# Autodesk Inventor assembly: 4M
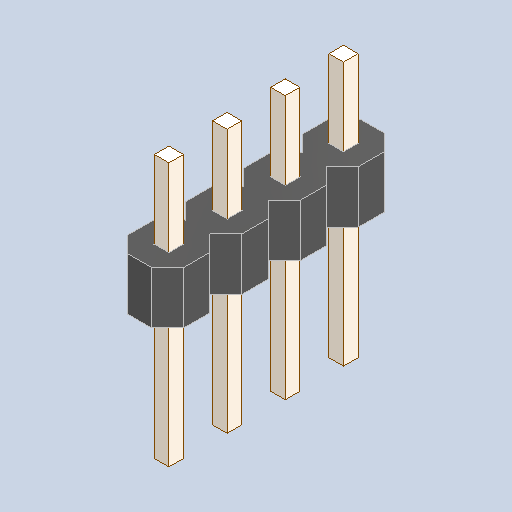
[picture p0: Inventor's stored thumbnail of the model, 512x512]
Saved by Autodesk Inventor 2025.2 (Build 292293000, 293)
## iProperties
Created: 2025-04
Part Number: 4M
Description: PART--DESC
Document SubType Name: Assembly
Designer: BennF
Author: BennF
Revision Number: NONE
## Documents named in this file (3)
- C:\Users\BennF\Nextcloud\Benutzer\CNC JarBeRi\existing parts\Electronics\RepRap A4988 Shied (USE WITHOUT ARDUINO)\reprap-a4988-1.snapshot.1\RepRap\RepRap\4M_2.iam
- C:\Users\BennF\Nextcloud\Benutzer\CNC JarBeRi\existing parts\Electronics\RepRap A4988 Shied (USE WITHOUT ARDUINO)\reprap-a4988-1.snapshot.1\RepRap\RepRap\4M Geometry.ipt
- C:\Users\BennF\Nextcloud\Benutzer\CNC JarBeRi\existing parts\Electronics\RepRap A4988 Shied (USE WITHOUT ARDUINO)\reprap-a4988-1.snapshot.1\RepRap\RepRap\Pin5.ipt
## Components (2 placed, 2 different names)
1. 4M Geometry
2. Pin5
